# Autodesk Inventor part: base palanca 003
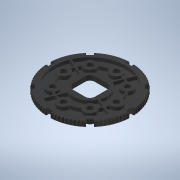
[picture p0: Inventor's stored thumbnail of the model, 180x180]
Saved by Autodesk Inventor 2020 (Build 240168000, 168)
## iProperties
Created: 2018-10
Part Number: base palanca 003
Material: Genérico
Document SubType Name: Modeling
Designer: Pedro
Density: 1 g/cm^3
Appearance: Por defecto
Author: Pedro
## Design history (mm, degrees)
sketch "Boceto1"
  geometry: L1 (-9.465, -19.581)-(-12.336, -26.511); L2 (-11.412, -26.894)-(-8.541, -19.964); L3 (27.509, -10.007)-(20.579, -7.137); L4 (20.196, -8.06)-(27.126, -10.931); L5 (8.675, 21.601)-(11.546, 28.531); L6 (10.622, 28.914)-(7.752, 21.983); L7 (-20.986, 10.08)-(-27.916, 12.951); L8 (-28.299, 12.027)-(-21.368, 9.156); L9 (5.421, 13.744)-(8.293, 20.676); L10 (7.369, 21.059)-(4.498, 14.127); L11 (-13.129, 6.826)-(-20.061, 9.697); L12 (-20.444, 8.773)-(-13.512, 5.902); L13 (-6.211, -11.725)-(-9.082, -18.657); L14 (-8.158, -19.04)-(-5.287, -12.108); L15 (12.34, -4.806)-(19.272, -7.678); L16 (19.655, -6.754)-(12.723, -3.883); L17 (-23.312, 27.463)-(-21.54, 25.69); L18 (-25.075, 22.155)-(-26.848, 23.927); L19 (-35.305, 3.51)-(-32.798, 3.51); L20 (-22.395, 3.51)-(-21.749, 3.51); L21 (-35.305, -1.49)-(-32.798, -1.49); L22 (-2.895, 35.92)-(-2.895, 33.413); L23 (2.105, 35.92)-(2.105, 33.413); L24 (12.937, 17.877)-(13.394, 18.334); L25 (20.75, 25.69)-(22.523, 27.463); L26 (26.059, 23.927)-(24.286, 22.155); L27 (16.929, 14.798)-(16.473, 14.342); L28 (32.009, 3.51)-(34.516, 3.51); L29 (32.009, -1.49)-(34.516, -1.49); L30 (24.286, -20.135)-(26.059, -21.908); L31 (22.523, -25.444)-(20.75, -23.671); L32 (13.394, -16.314)-(12.937, -15.858); L33 (2.105, -20.344)-(2.105, -20.99); L34 (2.105, -31.394)-(2.105, -33.901); L35 (-2.895, -20.99)-(-2.895, -21.351); L36 (-2.895, -31.394)-(-2.895, -33.901); L37 (-26.848, -21.908)-(-25.075, -20.135); L38 (-21.54, -23.671)-(-23.312, -25.444); L39 (20.959, -1.49)-(21.605, -1.49); L40 (20.959, 3.51)-(21.605, 3.51); L41 (-5.895, 10.51)-(5.105, 10.51); L42 (9.105, 6.51)-(9.105, -4.49); L43 (5.105, -8.49)-(-5.895, -8.49); L44 (-9.895, -4.49)-(-9.895, 6.51); L45 (-5.895, 10.51)-(-2.895, 10.51); C1 r 2.5 at (-0.395, 23.01); C2 r 2.5 at (-15.951, -14.547); C3 r 2.5 at (-15.951, 16.566); A1 r 2.5 centre (15.162, 16.566) between (16.929, 14.798) and (13.394, 18.334); A2 r 2.5 centre (-0.395, -20.99) between (2.105, -20.99) and (-2.895, -20.99); A3 r 2.5 centre (21.605, 1.01) between (21.605, -1.49) and (21.605, 3.51); A4 r 5 centre (-0.395, 23.01) between (-5.281, 21.947) and (4.491, 21.947); A5 r 5 centre (-0.395, 23.01) between (4.605, 22.947) and (-5.394, 22.947); A6 r 22.5 centre (-0.395, 1.01) between (-5.394, 22.947) and (-12.372, 20.057); A7 r 21.5 centre (-0.395, 1.01) between (-5.281, 21.947) and (-11.745, 19.27); A8 r 5 centre (-15.951, 16.566) between (-12.372, 20.057) and (-19.442, 12.987); A9 r 5 centre (-15.951, 16.566) between (-18.655, 12.36) and (-11.745, 19.27); A10 r 21.5 centre (-0.395, 1.01) between (-21.332, -3.876) and (-18.655, -10.341); A11 r 22.5 centre (-0.395, 1.01) between (-22.332, -3.99) and (-19.442, -10.967); A12 r 5 centre (-0.395, -20.99) between (-5.394, -20.928) and (4.605, -20.928); A13 r 5 centre (-0.395, -20.99) between (4.491, -19.928) and (-5.281, -19.928); A14 r 21.5 centre (-0.395, 1.01) between (4.491, -19.928) and (10.956, -17.25); A15 r 22.5 centre (-0.395, 1.01) between (4.605, -20.928) and (11.582, -18.038); A16 r 5 centre (-15.951, -14.547) between (-11.745, -17.25) and (-18.655, -10.341); A17 r 5 centre (-15.951, -14.547) between (-19.442, -10.967) and (-12.372, -18.038); A18 r 5 centre (-22.395, 1.01) between (-22.332, 6.009) and (-22.332, -3.99); A19 r 5 centre (-22.395, 1.01) between (-21.332, -3.876) and (-21.332, 5.896); A20 r 5 centre (15.162, 16.566) between (18.653, 12.987) and (11.582, 20.057); A21 r 5 centre (15.162, 16.566) between (10.956, 19.27) and (17.865, 12.36); A22 r 21.5 centre (-0.395, 1.01) between (20.543, 5.896) and (17.865, 12.36); A23 r 22.5 centre (-0.395, 1.01) between (21.543, 6.009) and (18.653, 12.987); A24 r 5 centre (21.605, 1.01) between (20.543, 5.896) and (20.543, -3.876); A25 r 5 centre (21.605, 1.01) between (21.543, -3.99) and (21.543, 6.009); A26 r 21.5 centre (-0.395, 1.01) between (-11.745, -17.25) and (-9.082, -18.657); A27 r 21.5 centre (-0.395, 1.01) between (-8.158, -19.04) and (-5.281, -19.928); A28 r 21.5 centre (-0.395, 1.01) between (10.956, 19.27) and (8.293, 20.676); A29 r 21.5 centre (-0.395, 1.01) between (7.369, 21.059) and (4.491, 21.947); A30 r 21.5 centre (-0.395, 1.01) between (-18.655, 12.36) and (-20.061, 9.697); A31 r 21.5 centre (-0.395, 1.01) between (-20.444, 8.773) and (-21.332, 5.896); A32 r 21.5 centre (-0.395, 1.01) between (19.655, -6.754) and (20.543, -3.876); A33 r 22.5 centre (-0.395, 1.01) between (-12.372, -18.038) and (-9.465, -19.581); A34 r 22.5 centre (-0.395, 1.01) between (-8.541, -19.964) and (-5.394, -20.928); A35 r 22.5 centre (-0.395, 1.01) between (18.653, -10.967) and (20.196, -8.06); A36 r 22.5 centre (-0.395, 1.01) between (20.579, -7.137) and (21.543, -3.99); A37 r 22.5 centre (-0.395, 1.01) between (11.582, 20.057) and (8.675, 21.601); A38 r 22.5 centre (-0.395, 1.01) between (7.752, 21.983) and (4.605, 22.947); A39 r 22.5 centre (-0.395, 1.01) between (-19.442, 12.987) and (-20.986, 10.08); A40 r 22.5 centre (-0.395, 1.01) between (-21.368, 9.156) and (-22.332, 6.009); A41 r 32.5 centre (-0.395, 1.01) between (-21.54, 25.69) and (-25.075, 22.155); A42 r 35 centre (-0.395, 1.01) between (-2.895, 35.92) and (-23.312, 27.463); A43 r 32.5 centre (-0.395, 1.01) between (2.105, 33.413) and (-2.895, 33.413); A44 r 35 centre (-0.395, 1.01) between (22.523, 27.463) and (2.105, 35.92); A45 r 32.5 centre (-0.395, 1.01) between (24.286, 22.155) and (20.75, 25.69); A46 r 30 centre (-0.395, 1.01) between (10.622, 28.914) and (-27.916, 12.951); A47 r 30 centre (-0.395, 1.01) between (-28.299, 12.027) and (11.546, 28.531); A48 r 32.5 centre (-0.395, 1.01) between (-32.798, 3.51) and (-32.798, -1.49); A49 r 35 centre (-0.395, 1.01) between (-26.848, 23.927) and (-35.305, 3.51); A50 r 35 centre (-0.395, 1.01) between (34.516, 3.51) and (26.059, 23.927); A51 r 35 centre (-0.395, 1.01) between (26.059, -21.908) and (34.516, -1.49); A52 r 32.5 centre (-0.395, 1.01) between (32.009, -1.49) and (32.009, 3.51); A53 r 32.5 centre (-0.395, 1.01) between (20.75, -23.671) and (24.286, -20.135); A54 r 5 centre (15.162, -14.547) between (11.582, -18.038) and (18.653, -10.967); A55 r 5 centre (15.162, -14.547) between (17.865, -10.341) and (10.956, -17.25); A56 r 35 centre (-0.395, 1.01) between (2.105, -33.901) and (22.523, -25.444); A57 r 32.5 centre (-0.395, 1.01) between (-25.075, -20.135) and (-21.54, -23.671); A58 r 32.5 centre (-0.395, 1.01) between (-2.895, -31.394) and (2.105, -31.394); A59 r 35 centre (-0.395, 1.01) between (-35.305, -1.49) and (-26.848, -21.908); A60 r 35 centre (-0.395, 1.01) between (-23.312, -25.444) and (-2.895, -33.901); A61 r 14 centre (-0.395, 1.01) between (-5.287, -12.108) and (12.34, -4.806); A62 r 14 centre (-0.395, 1.01) between (12.723, -3.883) and (5.421, 13.744); A63 r 14 centre (-0.395, 1.01) between (4.498, 14.127) and (-13.129, 6.826); A64 r 14 centre (-0.395, 1.01) between (-13.512, 5.902) and (-6.211, -11.725)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; 2 further points
  constraints: 141 point on circle, 90 end point, 71 centre point, 15 parallel, 11 coincident, 4 tangent, 1 horizontal, 1 vertical alignment, 16 other
extrude "Extrusión1" new body sketch "Boceto1" distance "d41" = 3; taper "d42" = 0 deg
sketch "Boceto2"
  geometry: L1 (2.895, 33.413)-(2.895, 35.92) reference; L2 (-2.105, 35.92)-(-2.105, 33.413) reference; L3 (-20.75, 25.69)-(-22.523, 27.463) reference; L4 (-26.059, 23.927)-(-24.286, 22.155) reference; L5 (-32.009, 3.51)-(-34.516, 3.51) reference; L6 (-34.516, -1.49)-(-32.009, -1.49) reference; L7 (-24.286, -20.135)-(-26.059, -21.908) reference; L8 (-22.523, -25.444)-(-20.75, -23.671) reference; L9 (-2.105, -31.394)-(-2.105, -33.901) reference; L10 (2.895, -33.901)-(2.895, -31.394) reference; L11 (21.54, -23.671)-(23.312, -25.444) reference; L12 (26.848, -21.908)-(25.075, -20.135) reference; L13 (32.798, -1.49)-(35.305, -1.49) reference; L14 (35.305, 3.51)-(32.798, 3.51) reference; L15 (25.075, 22.155)-(26.848, 23.927) reference; L16 (23.312, 27.463)-(21.54, 25.69) reference; A1 r 35 centre (0.395, 1.01) between (23.312, 27.463) and (2.895, 35.92) reference; A2 r 32.5 centre (0.395, 1.01) between (2.895, 33.413) and (-2.105, 33.413) reference; A3 r 35 centre (0.395, 1.01) between (-2.105, 35.92) and (-22.523, 27.463) reference; A4 r 32.5 centre (0.395, 1.01) between (-20.75, 25.69) and (-24.286, 22.155) reference; A5 r 35 centre (0.395, 1.01) between (-26.059, 23.927) and (-34.516, 3.51) reference; A6 r 32.5 centre (0.395, 1.01) between (-32.009, 3.51) and (-32.009, -1.49) reference; A7 r 35 centre (0.395, 1.01) between (-34.516, -1.49) and (-26.059, -21.908) reference; A8 r 32.5 centre (0.395, 1.01) between (-24.286, -20.135) and (-20.75, -23.671) reference; A9 r 35 centre (0.395, 1.01) between (-22.523, -25.444) and (-2.105, -33.901) reference; A10 r 32.5 centre (0.395, 1.01) between (-2.105, -31.394) and (2.895, -31.394) reference; A11 r 35 centre (0.395, 1.01) between (2.895, -33.901) and (23.312, -25.444) reference; A12 r 32.5 centre (0.395, 1.01) between (21.54, -23.671) and (25.075, -20.135) reference; A13 r 35 centre (0.395, 1.01) between (26.848, -21.908) and (35.305, -1.49) reference; A14 r 32.5 centre (0.395, 1.01) between (32.798, -1.49) and (32.798, 3.51) reference; A15 r 35 centre (0.395, 1.01) between (35.305, 3.51) and (26.848, 23.927) reference; A16 r 32.5 centre (0.395, 1.01) between (25.075, 22.155) and (21.54, 25.69) reference
extrude "Extrusión2" join sketch "Boceto2" distance "d44" = 2; taper "d45" = 0 deg
sketch "Boceto3"
  geometry: L1 (-20.75, 25.69)-(-18.977, 23.917); L2 (-24.286, 22.155)-(-22.512, 20.381); L3 (2.895, 33.413)-(2.895, 30.905); L4 (-2.105, 33.413)-(-2.105, 30.905); L5 (21.54, 25.69)-(19.766, 23.917); L6 (25.075, 22.155)-(23.302, 20.381); L7 (-32.009, 3.51)-(-29.501, 3.51); L8 (-32.009, -1.49)-(-29.501, -1.49); L9 (-20.75, -23.671)-(-18.977, -21.897); L10 (-24.286, -20.135)-(-22.512, -18.362); L11 (-2.105, -31.394)-(-2.105, -28.886); L12 (2.895, -31.394)-(2.895, -28.886); L13 (21.54, -23.671)-(19.766, -21.897); L14 (25.075, -20.135)-(23.302, -18.362); L15 (32.798, 3.51)-(30.29, 3.51); L16 (32.798, -1.49)-(30.29, -1.49); A1 r 32.5 centre (0.395, 1.01) between (2.895, 33.413) and (-2.105, 33.413) reference; A2 r 32.5 centre (0.395, 1.01) between (25.075, 22.155) and (21.54, 25.69) reference; A3 r 32.5 centre (0.395, 1.01) between (21.54, -23.671) and (25.075, -20.135); A4 r 30 centre (0.395, 1.01) between (2.895, -28.886) and (19.766, -21.897); A5 r 32.5 centre (0.395, 1.01) between (-2.105, -31.394) and (2.895, -31.394); A6 r 30 centre (0.395, 1.01) between (-18.977, -21.897) and (-2.105, -28.886); A7 r 32.5 centre (0.395, 1.01) between (-24.286, -20.135) and (-20.75, -23.671); A8 r 30 centre (0.395, 1.01) between (-29.501, -1.49) and (-22.512, -18.362); A9 r 32.5 centre (0.395, 1.01) between (-32.009, 3.51) and (-32.009, -1.49); A10 r 30 centre (0.395, 1.01) between (-22.512, 20.381) and (-29.501, 3.51); A11 r 30 centre (0.395, 1.01) between (-2.105, 30.905) and (-18.977, 23.917); A12 r 32.5 centre (0.395, 1.01) between (-20.75, 25.69) and (-24.286, 22.155); A13 r 32.5 centre (0.395, 1.01) between (2.895, 33.413) and (-2.105, 33.413); A14 r 32.5 centre (0.395, 1.01) between (32.798, -1.49) and (32.798, 3.51); A15 r 32.5 centre (0.395, 1.01) between (25.075, 22.155) and (21.54, 25.69); A16 r 30 centre (0.395, 1.01) between (19.766, 23.917) and (2.895, 30.905); A17 r 30 centre (0.395, 1.01) between (23.302, -18.362) and (30.29, -1.49); A18 r 30 centre (0.395, 1.01) between (30.29, 3.51) and (23.302, 20.381); 1 further point
  constraints: 33 end point, 32 point on circle, 16 centre point, 9 equal length, 5 perpendicular, 2 coincident
extrude "Extrusión3" cut sketch "Boceto3" distance "d47" = 1; taper "d48" = 0 deg
sketch "Boceto4"
  geometry: C1 r 4 at (0.395, 23.01); C2 r 4 at (15.951, 16.566); C3 r 4 at (-15.162, 16.566); C4 r 4 at (-21.605, 1.01); C5 r 4 at (-15.162, -14.547); C6 r 4 at (0.395, -20.99); C7 r 4 at (15.951, -14.547); C8 r 4 at (22.395, 1.01); 2 further points
  constraints: 8 centre point
  dimensions: "d50" = 8 diameter of C1; "d51" = 8 diameter of C2; "d52" = 8 diameter of C3; "d53" = 8 diameter of C4; "d54" = 8 diameter of C5; "d55" = 8 diameter of C6; "d56" = 8 diameter of C7; "d57" = 8 diameter of C8
extrude "Extrusión4" join sketch "Boceto4" distance "d58" = 0.5; taper "d59" = 0 deg
sketch "Boceto5"
  geometry: C1 r 22.5 at (0.395, 1.01); C2 r 21.5 at (0.395, 1.01); A1 r 30 centre (0.395, 1.01) between (19.766, 23.917) and (2.895, 30.905) reference; 1 further point
  constraints: 2 centre point, 2 coincident
  dimensions: "d60" = 45 diameter of C1; "d61" = 43 diameter of C2
extrude "Extrusión5" join sketch "Boceto5" distance "d62" = 1; taper "d63" = 0 deg
sketch "Boceto6"
  geometry: L1 (5.105, 10.51)-(-5.895, 10.51) reference; L2 (-5.895, -8.49)-(5.105, -8.49) reference; L3 (9.105, -4.49)-(9.105, 6.51) reference; L4 (-5.895, 10.51)-(5.105, 10.51); L5 (9.105, 6.51)-(9.105, -4.49); L6 (5.105, -8.49)-(-5.895, -8.49); L7 (-9.895, -4.49)-(-9.895, 6.51); L8 (9.105, 6.51)-(9.105, -4.49); A1 r 4 centre (5.105, 6.51) between (9.105, 6.51) and (5.105, 10.51) reference; A2 r 4 centre (-5.895, 6.51) between (-5.895, 10.51) and (-9.895, 6.51) reference; A3 r 4 centre (-5.895, -4.49) between (-9.895, -4.49) and (-5.895, -8.49) reference; A4 r 4 centre (5.105, -4.49) between (5.105, -8.49) and (9.105, -4.49) reference; A5 r 4 centre (-5.895, 6.51) between (-5.895, 10.51) and (-9.895, 6.51); A6 r 4 centre (-5.895, -4.49) between (-9.895, -4.49) and (-5.895, -8.49); A7 r 4 centre (5.105, 6.51) between (9.105, 6.51) and (5.105, 10.51); A8 r 4 centre (5.105, -4.49) between (5.105, -8.49) and (9.105, -4.49); 1 further point
  constraints: 20 tangent, 11 end point, 8 point on circle, 4 centre point, 4 coincident, 4 collinear, 3 concentric, 1 perpendicular
extrude "Extrusión6" cut sketch "Boceto6" distance "d64" = 2; taper "d65" = 0 deg
sketch "Boceto7"
  geometry: L1 (-35.038, -3.971)-(-33.854, -5.027); L2 (-33.854, -5.027)-(-34.595, -6.431); L3 (-33.339, -7.399)-(-33.977, -8.851); L4 (-34.595, -6.43)-(-33.339, -7.399); L5 (-32.655, -9.728)-(-33.188, -11.222); L6 (-33.977, -8.851)-(-32.655, -9.728); L7 (-31.806, -12.002)-(-32.232, -13.53); L8 (-33.188, -11.222)-(-31.806, -12.002); L9 (-30.798, -14.21)-(-31.113, -15.764); L10 (-32.232, -13.53)-(-30.798, -14.21); L11 (-29.635, -16.34)-(-29.838, -17.913); L12 (-31.113, -15.764)-(-29.635, -16.34); L13 (-28.323, -18.382)-(-28.413, -19.965); L14 (-29.839, -17.913)-(-28.323, -18.382); L15 (-26.868, -20.324)-(-26.846, -21.911); L16 (-28.414, -19.965)-(-26.868, -20.324); L17 (-25.279, -22.159)-(-25.143, -23.739); L18 (-26.846, -21.911)-(-25.279, -22.159); L19 (-23.563, -23.875)-(-23.314, -25.442); L20 (-25.143, -23.739)-(-23.563, -23.875); L21 (-21.728, -25.464)-(-21.369, -27.01); L22 (-23.315, -25.442)-(-21.728, -25.464); L23 (-19.785, -26.919)-(-19.317, -28.434); L24 (-21.369, -27.009)-(-19.785, -26.919); L25 (-17.744, -28.231)-(-17.168, -29.709); L26 (-19.317, -28.434)-(-17.744, -28.231); L27 (-15.613, -29.394)-(-14.934, -30.828); L28 (-17.168, -29.709)-(-15.613, -29.394); L29 (-13.406, -30.402)-(-12.625, -31.784); L30 (-14.934, -30.827)-(-13.406, -30.402); L31 (-11.132, -31.25)-(-10.255, -32.573); L32 (-12.626, -31.784)-(-11.132, -31.25); L33 (-8.803, -31.934)-(-7.834, -33.191); L34 (-10.255, -32.573)-(-8.803, -31.934); L35 (-6.431, -32.45)-(-5.375, -33.634); L36 (-7.834, -33.19)-(-6.431, -32.45); L37 (-4.029, -32.795)-(-2.891, -33.901); L38 (-5.376, -33.634)-(-4.029, -32.795); L39 (-1.608, -32.969)-(-0.394, -33.99); L40 (-2.891, -33.901)-(-1.608, -32.969); L41 (0.819, -32.969)-(2.103, -33.901); L42 (-0.395, -33.99)-(0.819, -32.969); L43 (3.24, -32.795)-(4.587, -33.634); L44 (2.102, -33.901)-(3.24, -32.795); L45 (5.642, -32.45)-(7.046, -33.19); L46 (4.586, -33.634)-(5.642, -32.45); L47 (8.014, -31.934)-(9.466, -32.572); L48 (7.045, -33.19)-(8.014, -31.934); L49 (10.343, -31.25)-(11.837, -31.783); L50 (9.466, -32.572)-(10.343, -31.25); L51 (12.617, -30.402)-(14.145, -30.827); L52 (11.837, -31.783)-(12.617, -30.402); L53 (14.825, -29.394)-(16.379, -29.709); L54 (14.145, -30.827)-(14.825, -29.394); L55 (16.955, -28.231)-(18.528, -28.434); L56 (16.379, -29.709)-(16.955, -28.231); L57 (18.997, -26.918)-(20.58, -27.009); L58 (18.528, -28.434)-(18.997, -26.918); L59 (20.939, -25.464)-(22.526, -25.441); L60 (20.58, -27.009)-(20.939, -25.464); L61 (22.774, -23.874)-(24.354, -23.739); L62 (22.526, -25.441)-(22.774, -23.874); L63 (24.49, -22.158)-(26.057, -21.91); L64 (24.354, -23.739)-(24.49, -22.158)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; C1 r 37.5 at (-0.395, 1.01); 91 further points
  constraints: 352 end point, 1 centre point, 441 other
  dimensions: "d67" = 75 diameter of C1; "d73" = 360 deg dimension on point (-0.395, 1.01) L1.end (derived)
chamfer "Chaflán1" distance "d75" = 1; stored, may be unused: second distance "d76" = 2, angle "d77" = 45 deg
chamfer "Chaflán2" distance "d78" = 0.5; stored, may be unused: second distance "d79" = 2, angle "d80" = 45 deg
extrude "Extrusión7" cut sketch "Boceto7" distance "d81" = 10; taper "d82" = 0 deg
sketch "Boceto8"
  geometry: L1 (-5.403, 18.023)-(13.462, 18.023); L2 (13.462, 18.023)-(13.462, 10.052); L3 (13.462, 10.052)-(-5.403, 10.052); L4 (-5.403, 10.052)-(-5.403, 18.023); 1 further point
  constraints: 2 other
extrude "Extrusión8" join sketch "Boceto8" distance "d83" = 0.5; taper "d84" = 0 deg
fillet "Empalme1" dims "d85" = 0.4
node "Sólido1"
